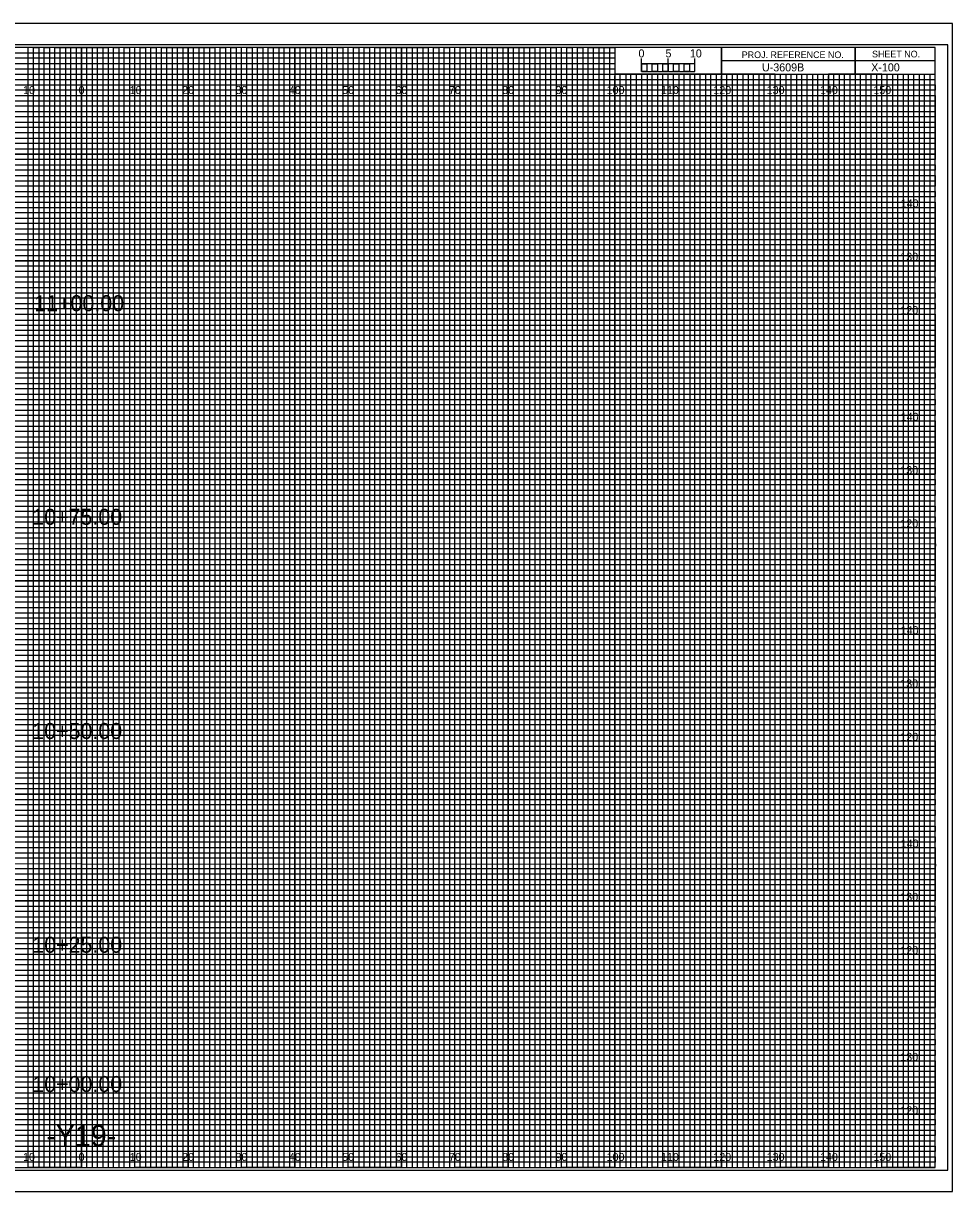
# Model space of a CAD drawing. Extents: x -13 to 323, y -5 to 654.
# Drawn here: x 149.1 to 323.3, y -4.5 to 214.5 of the extents above; entities that cross this region are included whole.
import ezdxf

# ---------------------------------------------------------------- set-up
doc = ezdxf.new("R2010")
doc.units = 0
for name, color, linetype in [('Prop XS Alignment Label', 7, 'Continuous'), ('Prop XS Bar Scale Labels', 7, 'Continuous'), ('Prop XS Elevation Labels', 7, 'Continuous'), ('Prop XS Offset Labels', 7, 'Continuous'), ('Prop XS Project Number', 7, 'Continuous'), ('Prop XS Sheet Number', 7, 'Continuous'), ('Prop XS Station Labels', 7, 'Continuous'), ('Sheet Cross Section CELL', 7, 'Continuous'), ('Sheet Cross Section Grid Major CELL', 7, 'Continuous'), ('Sheet Cross Section Grid Middle CELL', 7, 'Continuous'), ('Sheet Cross Section Grid Minor 1 CELL', 7, 'Continuous'), ('Sheet Cross Section Grid Minor 2 CELL', 7, 'Continuous'), ('Sheet Cross Section Scale CELL', 7, 'Continuous'), ('Sheet Cutting Line CELL', 7, 'Continuous'), ('Sheet DOT Grid CELL', 7, 'Continuous'), ('Sheet Plot Border Inside CELL', 7, 'Continuous'), ('Sheet Plot Border Outside CELL', 7, 'Continuous')]:
    doc.layers.add(name, color=color, linetype=linetype)

msp = doc.modelspace()

# ---------------------------------------------------------------- linework, layer by layer
at = {"layer": 'Sheet Cross Section CELL'}
for p, q in [((305, 210), (305, 205)), ((305, 205), (305, 210)), ((280, 207.5), (280, 205)), ((320, 207.49), (280, 207.49)), ((280, 205), (320, 205))]:
    msp.add_line(p, q, dxfattribs=at)
for points in [[(320, 210), (0, 210), (0, 0), (320, 0)], [(280, 210), (260, 210), (260, 205.03), (280, 205.03)], [(320, 210), (280, 210), (280, 205), (320, 205)]]:
    msp.add_lwpolyline(points, close=True, dxfattribs=at)
at = {"layer": 'Sheet Cross Section Grid Major CELL'}
for p, q in [((150, 210), (140, 210)), ((150, 0), (150, 210)), ((170, 210), (160, 210)), ((160, 210), (160, 0)), ((170, 0), (170, 210)), ((190, 210), (180, 210)), ((180, 210), (180, 0)), ((190, 0), (190, 210)), ((210, 210), (200, 210)), ((200, 210), (200, 0)), ((210, 0), (210, 210)), ((230, 210), (220, 210)), ((220, 210), (220, 0)), ((230, 0), (230, 210)), ((250, 210), (240, 210)), ((240, 210), (240, 0)), ((250, 0), (250, 210)), ((260, 210), (260, 0)), ((270, 0), (270, 205)), ((290, 205), (280, 205)), ((280, 205), (280, 0)), ((290, 0), (290, 205)), ((310, 205), (300, 205)), ((300, 205), (300, 0)), ((310, 0), (310, 205)), ((160, 0), (150, 0)), ((180, 0), (170, 0)), ((200, 0), (190, 0)), ((220, 0), (210, 0)), ((240, 0), (230, 0)), ((260, 0), (250, 0)), ((280, 0), (270, 0)), ((300, 0), (290, 0)), ((320, 0), (310, 0)), ((320, 0), (320, 0))]:
    msp.add_line(p, q, dxfattribs=at)
for points in [[(0, 200), (320, 200), (320, 190), (0, 190)], [(0, 180), (320, 180), (320, 170), (0, 170)], [(0, 160), (320, 160), (320, 150), (0, 150)], [(0, 140), (320, 140), (320, 130), (0, 130)], [(0, 120), (320, 120), (320, 110), (0, 110)], [(0, 100), (320, 100), (320, 90), (0, 90)], [(0, 80), (320, 80), (320, 70), (0, 70)], [(0, 60), (320, 60), (320, 50), (0, 50)], [(0, 40), (320, 40), (320, 30), (0, 30)], [(0, 20), (320, 20), (320, 10), (0, 10)]]:
    msp.add_lwpolyline(points, dxfattribs=at)
at = {"layer": 'Sheet Cross Section Grid Middle CELL'}
for points in [[(145, 0), (155, 0), (155, 210), (165, 210), (165, 0), (175, 0), (175, 210), (185, 210), (185, 0), (195, 0), (195, 210), (205, 210), (205, 0), (215, 0), (215, 210), (225, 210), (225, 0), (235, 0), (235, 210), (245, 210), (245, 0), (255, 0), (255, 210), (259.93, 210), (260, 210), (260, 205), (264.99, 205), (264.99, 0), (275, 0), (275, 205), (285, 205), (285, 0), (295, 0), (295, 205), (305, 205), (305, 0), (315, 0), (315, 205)], [(0, 205), (275, 205)], [(0, 185), (320, 185), (320, 195), (0, 195)], [(0, 165), (320, 165), (320, 175), (0, 175)], [(0, 145), (320, 145), (320, 155), (0, 155)], [(0, 125), (320, 125), (320, 135), (0, 135)], [(0, 105), (320, 105), (320, 115), (0, 115)], [(0, 85), (320, 85), (320, 95), (0, 95)], [(0, 65), (320, 65), (320, 75), (0, 75)], [(0, 45), (320, 45), (320, 55), (0, 55)], [(0, 25), (320, 25), (320, 35), (0, 35)], [(0, 5), (320, 5), (320, 15), (0, 15)]]:
    msp.add_lwpolyline(points, dxfattribs=at)
at = {"layer": 'Sheet Cross Section Grid Minor 1 CELL'}
for p, q in [((0, 209), (260, 209)), ((260, 209), (260, 207.98)), ((260, 207.98), (0, 207.98)), ((0, 207), (260, 207)), ((260, 205.89), (0, 205.89)), ((260, 207), (260, 205.89)), ((0, 204), (320, 204))]:
    msp.add_line(p, q, dxfattribs=at)
for points in [[(0, 203), (270, 203), (320, 203), (320, 202), (0, 202)], [(0, 201), (320, 201), (320, 199), (0, 199)], [(0, 198), (320, 198), (320, 197), (0, 196.98)], [(0, 196), (320, 196), (320, 194), (0, 194)], [(0, 193), (320, 193), (320, 192), (0, 192)], [(0, 191), (320, 191), (320, 189), (0, 189)], [(0, 188), (320, 188), (320, 187), (0, 187)], [(0, 186), (320, 186), (320, 184), (0, 184)], [(0, 183), (320, 183), (320, 182), (0, 182)], [(0, 181), (320, 181), (320, 179), (0, 179)], [(0, 178), (320, 178), (320, 177), (0, 177)], [(0, 176), (320, 176), (320, 173.95), (320, 173), (320, 172), (0, 172)], [(0, 174), (320, 174), (320, 173), (0, 173)], [(0, 171), (320, 171), (320, 169), (0, 169.03)], [(0, 169.03), (320, 169), (320, 168), (0, 168)], [(0, 167), (320, 167), (320, 166), (0, 166)], [(0, 164), (320, 164), (320, 163), (0, 163)], [(0, 162), (320, 162), (320, 161), (0, 161)], [(-0.07, 158.89), (320, 158.89), (320, 157.88), (-0.07, 157.88)], [(0, 157), (320, 157), (320, 156), (0, 156)], [(0, 154), (320, 154), (320, 153), (0, 153)], [(0, 152), (320, 152), (320, 151), (0, 151)], [(0, 149), (320, 149), (320, 148), (0, 148)], [(0, 147), (320, 147), (320, 146), (0, 146)], [(0, 144), (320, 144), (320, 143), (0, 143)], [(0, 142), (320, 142), (320, 141), (0, 141)], [(0, 139), (320, 139), (319.99, 137.98), (0, 138)], [(0, 137), (320, 137), (320, 136), (0, 136)], [(0, 134), (320, 134), (320, 133), (0, 133)], [(0, 132), (320, 132), (320, 131), (0, 131)], [(0, 129), (320, 129), (320, 128), (0, 128)], [(0, 127), (320, 127), (320, 126), (0, 126)], [(0, 124), (320, 124), (320, 123), (0, 123)], [(0, 122), (320, 122), (320, 121), (0, 121)], [(0, 119), (320, 119), (320, 118), (0, 118)], [(0, 116.99), (320.07, 116.91), (320, 116), (0, 116)], [(0, 114), (320, 114), (320, 113), (0, 113)], [(0, 112), (320, 112), (320, 111), (0, 111)], [(0, 109), (320, 109), (320, 108), (0, 108)], [(0, 107), (320, 107), (320, 106), (0, 106)], [(0, 104), (320, 104), (320, 103), (0, 103)], [(0, 102), (320, 102), (320, 101), (0, 101)], [(0, 99), (320, 99), (320, 98), (0, 98)], [(0, 97), (320, 97), (320, 96), (0, 96)], [(0, 94), (320, 94), (320, 93), (0, 93)], [(0, 92), (320, 92), (320, 91), (0, 91)], [(0, 89), (320, 89), (320, 88), (0, 88)], [(0, 87), (320, 87), (320, 86), (0, 86)], [(0, 84), (320, 84), (320, 83), (0, 83)], [(0, 82), (320, 82), (320, 81), (0, 81)], [(0, 79), (320, 79), (319.99, 77.98), (0, 78)], [(0, 77), (320, 77), (320, 76), (0, 76)], [(0, 74), (320, 74), (320, 73), (0, 73)], [(0, 72), (320, 72), (320, 71), (0, 71)], [(0, 69), (320, 69), (320, 68), (0, 68)], [(0, 67), (320, 67), (320, 66), (0, 66)], [(0, 64), (320, 64), (320, 63), (0, 63)], [(0, 62), (320, 62), (320, 61), (0, 61)], [(0, 59), (320, 59), (320, 58), (0, 58)], [(0, 56.99), (320.07, 56.91), (320, 56), (0, 56)], [(0, 54), (320, 54), (320, 53), (0, 53)], [(0, 52), (320, 52), (320, 51), (0, 51)], [(0, 49), (320, 49), (320, 48), (0, 48)], [(0, 47), (320, 47), (320, 46), (0, 46)], [(0, 44), (320, 44), (320, 43), (0, 43)], [(0, 42), (320, 42), (320, 41), (0, 41)], [(0, 39), (320, 39), (320, 38), (0, 38)], [(0, 37), (320, 37), (320, 36), (0, 36)], [(0, 34), (320, 34), (320, 33), (0, 33)], [(0, 32), (320, 32), (320, 31), (0, 31)], [(0, 29), (320, 29), (320, 28), (0, 28)], [(0, 27), (320, 27), (320, 26), (0, 26)], [(0, 24), (320, 24), (320, 23), (0, 23)], [(0, 22), (320, 22), (320, 21), (0, 21)], [(0, 19), (320, 19), (320, 18), (0, 18)], [(0, 17), (320, 17), (320, 16), (0, 16)], [(0, 14), (320, 14), (320, 13), (0, 13)], [(0, 12), (320, 12), (320, 11), (0, 11)], [(0, 9), (320, 9), (320, 8), (0, 8)], [(0, 7), (320, 7), (320, 6), (0, 6)], [(0, 4), (320, 4), (320, 3), (0, 3)], [(0, 2), (320, 2), (320, 1), (0, 1)]]:
    msp.add_lwpolyline(points, dxfattribs=at)
at = {"layer": 'Sheet Cross Section Grid Minor 2 CELL'}
for p, q in [((267, 205), (266.01, 205)), ((266.01, 205), (266.01, 0)), ((267, 0), (267, 205)), ((269, 205), (268, 205)), ((268, 205), (268, 0)), ((269, 0), (269, 205)), ((266.01, 0), (265, 0)), ((268, 0), (267, 0))]:
    msp.add_line(p, q, dxfattribs=at)
for points in [[(150, 0), (151, 0), (151, 210), (152, 210), (152, 0)], [(152, 0), (153, 0), (153, 210), (154, 210), (154, 0)], [(155, 0), (156, 0), (156, 210), (157, 210), (157, 0)], [(157, 0), (158, 0), (158, 210), (159, 210), (159, 0)], [(160, 0), (161, 0), (161, 210), (162, 210), (162, 0)], [(162, 0), (163, 0), (163, 210), (164, 210), (164, 0)], [(165, 0), (166, 0), (166, 210), (167, 210), (167, 0)], [(167, 0), (168, 0), (168, 210), (169, 210), (169, 0)], [(170, 0), (171, 0), (171, 210), (172, 210), (172, 0)], [(172, 0), (173, 0), (173, 210), (174, 210), (174, 0)], [(175, 0), (176, 0), (176, 210), (177, 210), (177, 0)], [(177, 0), (178, 0), (178, 210), (179, 210), (179, 0)], [(180, 0), (181, 0), (181, 210), (182, 210), (182, 0)], [(182, 0), (183, 0), (183, 210), (184, 210), (184, 0)], [(185, 0), (186, 0), (186, 210), (187, 210), (187, 0)], [(187, 0), (188, 0), (188, 210), (189, 210), (189, 0)], [(190, 0), (191, 0), (191, 210), (192, 210), (192, 0)], [(192, 0), (193, 0), (193, 210), (194, 210), (194, 0)], [(195, 0), (196, 0), (196, 210), (197, 210), (197, 0)], [(197, 0), (198, 0), (198, 210), (199, 210), (199, 0)], [(200, 0), (201, 0), (201, 210), (202, 210), (202, 0)], [(202, 0), (203, 0), (203, 210), (204, 210), (204, 0)], [(205, 0), (206, 0), (206, 210), (207, 210), (207, 0)], [(207, 0), (208, 0), (208, 210), (209, 210), (209, 0)], [(210, 0), (211, 0), (211, 210), (212, 210), (212, 0)], [(212, 0), (213, 0), (213, 210), (214, 210), (214, 0)], [(215, 0), (216, 0), (216, 210), (217, 210), (217, 0)], [(217, 0), (218, 0), (218, 210), (219, 210), (219, 0)], [(220, 0), (221, 0), (221, 210), (222, 210), (222, 0)], [(222, 0), (223, 0), (223, 210), (224, 210), (224, 0)], [(225, 0), (226, 0), (226, 210), (227, 210), (227, 0)], [(227, 0), (228, 0), (228, 210), (229, 210), (229, 0)], [(230, 0), (231, 0), (231, 210), (232, 210), (232, 0)], [(232, 0), (233, 0), (233, 210), (234, 210), (234, 0)], [(235, 0), (236, 0), (236, 210), (237, 210), (237, 0)], [(237, 0), (238, 0), (238, 210), (239, 210), (239, 0)], [(240, 0), (241, 0), (241, 210), (242, 210), (242, 0)], [(242, 0), (243, 0), (243, 210), (244, 210), (244, 0)], [(245, 0), (246, 0), (246, 210), (247, 210), (247, 0)], [(247, 0), (248, 0), (248, 210), (249, 210), (249, 0)], [(250, 0), (251, 0), (251, 210), (252, 210), (252, 0)], [(252, 0), (253, 0), (253, 210), (254, 210), (254, 0)], [(255, 0), (256, 0), (256, 210), (257, 210), (257, 0)], [(257, 0), (258, 0), (258, 210), (259, 210), (259, 0)], [(260, 0), (261, 0), (261, 205), (262.02, 205), (262.02, 0)], [(262, 0), (263, 0), (263, 205), (263.99, 205), (263.99, 0)], [(270, 0), (270.98, 0), (270.98, 205), (272, 205), (272, 0)], [(272, 0), (273, 0), (273, 205), (274.05, 205), (274.05, 0)], [(275, 0), (276, 0), (276, 205), (277, 205), (277, 0)], [(277, 0), (278, 0), (278, 205), (279, 205), (279, 0)], [(280, 0), (281, 0), (281, 205), (282, 205), (282, 0)], [(282, 0), (283, 0), (283, 205), (284, 205), (284, 0)], [(285, 0), (286, 0), (286, 205), (287, 205), (287, 0)], [(287, 0), (288, 0), (288, 205), (289, 205), (289, 0)], [(290, 0), (291, 0), (291, 205), (292, 205), (292, 0)], [(292, 0), (293, 0), (293, 205), (294, 205), (294, 0)], [(295, 0), (296, 0), (296, 205), (297, 205), (297, 0)], [(297, 0), (298, 0), (298, 205), (299, 205), (299, 0)], [(300, 0), (301, 0), (301, 205), (302, 205), (302, 0)], [(302, 0), (303, 0), (303, 205), (304, 205), (304, 0)], [(305, 0), (306, 0), (306, 205), (307, 205), (307, 0)], [(307, 0), (308, 0), (308, 205), (309, 205), (309, 0)], [(310, 0), (311, 0), (311, 205), (312, 205), (312, 0)], [(312, 0), (313, 0), (313, 205), (314, 205), (314, 0)], [(315, 0), (316, 0), (316, 205), (317, 205), (317, 0)], [(317, 0), (318, 0), (318, 205), (319, 205), (319, 0)]]:
    msp.add_lwpolyline(points, dxfattribs=at)
at = {"layer": 'Sheet Cross Section Scale CELL'}
for p, q in [((265, 205.49), (265, 207.9)), ((265, 206.9), (265, 207.9)), ((270, 205.49), (270, 207.9)), ((275, 205.49), (275, 207.9)), ((275, 206.9), (275, 207.9))]:
    msp.add_line(p, q, dxfattribs=at)
for points in [[(275, 206.9), (265, 206.9), (265, 205.49), (275, 205.49)], [(265, 206.9), (266, 206.9), (266, 205.49), (265, 205.49)], [(267, 206.9), (268, 206.9), (268, 205.49), (267, 205.49)], [(269, 206.9), (270, 206.9), (270, 205.49), (269, 205.49)], [(271, 206.9), (272, 206.9), (272, 205.49), (271, 205.49)], [(273, 206.9), (274, 206.9), (274, 205.49), (273, 205.49)]]:
    msp.add_lwpolyline(points, close=True, dxfattribs=at)
at = {"layer": 'Sheet Cutting Line CELL'}
for p, q in [((323.3, 214.5), (-13.4, 214.5)), ((-13.4, -4.5), (323.3, -4.5))]:
    msp.add_line(p, q, dxfattribs=at)
at = {"layer": 'Sheet DOT Grid CELL'}
for p, q in [((150, 0), (150, 210)), ((160, 0), (160, 210)), ((170, 0), (170, 210)), ((180, 0), (180, 210)), ((190, 0), (190, 210)), ((200, 0), (200, 210)), ((210, 0), (210, 210)), ((220, 0), (220, 210)), ((230, 0), (230, 210)), ((240, 0), (240, 210)), ((250, 0), (250, 210)), ((260, 0), (260, 204.69)), ((270, 0), (270, 204.69)), ((280, 0), (280, 204.69)), ((290, 0), (290, 204.69)), ((300, 0), (300, 204.69)), ((310, 0), (310, 204.69)), ((0, 200), (320, 200)), ((0, 190), (320, 190)), ((0, 180), (320, 180)), ((0, 170), (320, 170)), ((0, 160), (320, 160)), ((0, 150), (320, 150)), ((0, 140), (320, 140)), ((0, 130), (320, 130)), ((0, 120), (320, 120)), ((0, 110), (320, 110)), ((0, 100), (320, 100)), ((0, 90), (320, 90)), ((0, 80), (320, 80)), ((0, 70), (320, 70)), ((0, 60), (320, 60)), ((0, 50), (320, 50)), ((0, 40), (320, 40)), ((0, 30), (320, 30)), ((0, 20), (320, 20)), ((0, 10), (320, 10))]:
    msp.add_line(p, q, dxfattribs=at)
at = {"layer": 'Sheet Plot Border Inside CELL'}
msp.add_lwpolyline([(-10.8, -0.5), (322.4, -0.5), (322.4, 210.5), (-10.8, 210.5)], close=True, dxfattribs=at)
at = {"layer": 'Sheet Plot Border Outside CELL'}
msp.add_lwpolyline([(-13.4, -4.5), (323.3, -4.5), (323.3, 214.5), (-13.4, 214.5)], close=True, dxfattribs=at)

# ---------------------------------------------------------------- texts
at = {"layer": 'Prop XS Alignment Label'}
msp.add_text('-Y19-', height=4, dxfattribs=at).set_placement((153.41, 4))
at = {"layer": 'Prop XS Bar Scale Labels'}
for s, p in [('5', (269.47, 208.12)), ('10', (274.04, 208.12))]:
    msp.add_text(s, height=1.5, dxfattribs=at).set_placement(p)
at = {"layer": 'Prop XS Elevation Labels'}
for s, p in [('140', (313.57, 180)), ('130', (313.49, 170)), ('120', (313.5, 160)), ('140', (313.57, 140)), ('130', (313.49, 130)), ('120', (313.5, 120)), ('140', (313.57, 100)), ('130', (313.49, 90)), ('120', (313.5, 80)), ('140', (313.57, 60)), ('130', (313.49, 50)), ('120', (313.5, 40)), ('130', (313.49, 20)), ('120', (313.5, 10))]:
    msp.add_text(s, height=1.5, dxfattribs=at).set_placement(p)
at = {"layer": 'Prop XS Offset Labels'}
for s, p in [('10', (149.04, 201.25)), ('0', (159.45, 201.25)), ('0', (159.45, 201.25)), ('10', (169.04, 201.25)), ('20', (178.86, 201.25)), ('30', (188.86, 201.25)), ('40', (198.86, 201.25)), ('50', (208.86, 201.25)), ('60', (218.86, 201.25)), ('70', (228.86, 201.25)), ('80', (238.86, 201.25)), ('90', (248.86, 201.25)), ('100', (258.44, 201.25)), ('110', (268.62, 201.25)), ('120', (278.44, 201.25)), ('130', (288.44, 201.25)), ('140', (298.44, 201.25)), ('150', (308.44, 201.25)), ('10', (149.04, 1.25)), ('0', (159.45, 1.25)), ('0', (159.45, 1.25)), ('10', (169.04, 1.25)), ('20', (178.86, 1.25)), ('30', (188.86, 1.25)), ('40', (198.86, 1.25)), ('50', (208.86, 1.25)), ('60', (218.86, 1.25)), ('70', (228.86, 1.25)), ('80', (238.86, 1.25)), ('90', (248.86, 1.25)), ('100', (258.44, 1.25)), ('110', (268.62, 1.25)), ('120', (278.44, 1.25)), ('130', (288.44, 1.25)), ('140', (298.44, 1.25)), ('150', (308.44, 1.25))]:
    msp.add_text(s, height=1.5, dxfattribs=at).set_placement(p)
at = {"layer": 'Prop XS Project Number'}
msp.add_text('U-3609B', height=1.5, dxfattribs=at).set_placement((287.56, 205.5))
at = {"layer": 'Prop XS Sheet Number'}
msp.add_text('X-100', height=1.5, dxfattribs=at).set_placement((308.03, 205.5))
at = {"layer": 'Prop XS Station Labels'}
for s, p in [('11+00.00', (151.13, 160.54)), ('10+75.00', (150.77, 120.5)), ('10+50.00', (150.77, 80.35)), ('10+25.00', (150.77, 40.28)), ('10+00.00', (150.77, 14.17))]:
    msp.add_text(s, height=3, dxfattribs=at).set_placement(p)
at = {"layer": 'Sheet Cross Section CELL'}
for s, p in [('PROJ. REFERENCE NO.', (283.77, 207.99)), ('SHEET NO.', (308.19, 208.12))]:
    msp.add_text(s, height=1.25, dxfattribs=at).set_placement(p)
at = {"layer": 'Sheet Cross Section Scale CELL'}
msp.add_text('0', height=1.5, dxfattribs=at).set_placement((264.41, 208.12))

doc.saveas('drawing.dxf')
